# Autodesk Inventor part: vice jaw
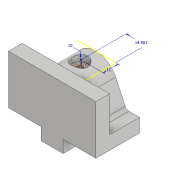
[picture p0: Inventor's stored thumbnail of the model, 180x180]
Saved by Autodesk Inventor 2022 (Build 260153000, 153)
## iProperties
Created: 2016-03
Part Number: vice jaw
Material: Generic
Document SubType Name: Modeling
Designer: Sandeep
Density: 1 g/cm^3
Appearance: Default
Mass: 55.5986 g
Surface Area: 129.526 cm^2
Volume: 55.5986 cm^3
Author: Sandeep
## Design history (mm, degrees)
sketch "Sketch1"
  geometry: L1 (0, 0)-(-32, 0); L2 (-32, 0)-(-32, 36); L3 (-32, 36)-(-22, 36); L4 (-22, 36)-(-22, 10); L5 (-22, 10)-(0, 10); L6 (0, 10)-(0, 0)
  constraints: 12 end point, 5 perpendicular, 1 horizontal
  dimensions: "d0" = 36 distance between parallel lines of L1 L3; "d1" = 32 distance of L1.start L1.end; "d2" = 10 distance of L5.end L1.start; "d3" = 10 distance of L2.end L3.end
extrude "Extrusion1" new body sketch "Sketch1" stored distance "d4" = 64; taper "d5" = 0 deg
sketch "Sketch2"
  geometry: L1 (64, 10)-(64, 0) reference; L2 (64, 10)-(64, 0); L3 (64, 0)-(54.317, 0); L4 (64, 0)-(0, 0) reference; L5 (54.317, 0)-(46.501, -16.762); L6 (0, 0)-(0, 10); L7 (0, 10)-(64, 10); L8 (64, -26)-(0, -26) reference; L9 (0, 0)-(9.683, 0); L10 (32, 10)-(32, -39.451); L11 (9.683, 0)-(17.499, -16.762); A1 r 16 centre (32, -10) between (17.499, -16.762) and (46.501, -16.762); 1 further point
  constraints: 16 end point, 3 point on line, 2 collinear, 2 perpendicular, 2 point on circle, 2 symmetric about line, 2 tangent, 1 centre point, 1 coincident, 1 vertical
  dimensions: "d8" = 16 radius of A1; "d9" = 50 deg angle of L11 L5
extrude "Extrusion2" join sketch "Sketch2" stored distance "d10" = 32; taper "d11" = 0 deg
fillet "Fillet1" dims "d12" = 3
sketch "Sketch3"
  geometry: L1 (40, 0)-(40, 9); L2 (40, 9)-(24, 9); L3 (24, 9)-(24, 0); L4 (24, 0)-(40, 0); L5 (0, 0)-(64, 0) reference; L6 (32, 0)-(32, -54.171)
  constraints: 10 end point, 2 perpendicular, 2 vertical, 1 collinear, 1 point on line, 1 other
  dimensions: "d13" = 16 distance between parallel lines of L3 L1; "d14" = 9 distance of L2.end L3.end
extrude "Extrusion3" join sketch "Sketch3" stored distance "d15" = 32; taper "d16" = 0 deg
sketch "Sketch4"
  geometry: L1 (-24, 19)-(-40, 19) reference; L2 (-32, 19)-(-32, -29.453); C1 r 6 at (-32, -10); A1 r 16 centre (-32, -10) between (-46.501, -16.762) and (-17.499, -16.762) reference; 1 further point
  constraints: 2 end point, 1 centre point, 1 concentric, 1 midpoint, 1 point on line, 1 vertical
  dimensions: "d17" = 12 diameter of C1
extrude "Extrusion4" cut sketch "Sketch4" distance "d18" = 24; taper "d19" = 0 deg
sketch "Sketch6"
  geometry: 1 further point
workplane "Work Plane1"
sketch "Sketch7"
  geometry: L1 (14.501, 0)-(-14.501, 0) reference; L2 (14.501, 0)-(14.501, -22) reference; C1 r 5 at (0, -11); 1 further point
  constraints: 1 centre point
  dimensions: "d22" = 10 diameter of C1; "d23" = 11 distance from line of L1 C1.centre; "d24" = 14.50092 distance from line of C1.centre L2
workplane "Work Plane2"
hole "Hole1" diameter "d37" = 4.917; stored, may be unused: countersink angle "d41" = 90 deg, drill point angle "d43" = 118 deg; dims "d35" = 8, "d36" = 8, "d38" = 12, "d39" = 4, "d40" = 2, "d42" = 16
hole "Hole2" diameter "d46" = 4.917; stored, may be unused: countersink angle "d50" = 90 deg, drill point angle "d52" = 118 deg; dims "d44" = 8, "d45" = 8, "d47" = 12, "d48" = 4, "d49" = 2, "d51" = 16
hole "Hole3" diameter "d55" = 4.917; stored, may be unused: countersink angle "d59" = 82 deg, drill point angle "d61" = 118 deg; dims "d53" = 20, "d54" = 32, "d56" = 12, "d57" = 12, "d58" = 5, "d60" = 17.1
sketch "Sketch10"
  geometry: 1 further point
body "Solid1"
